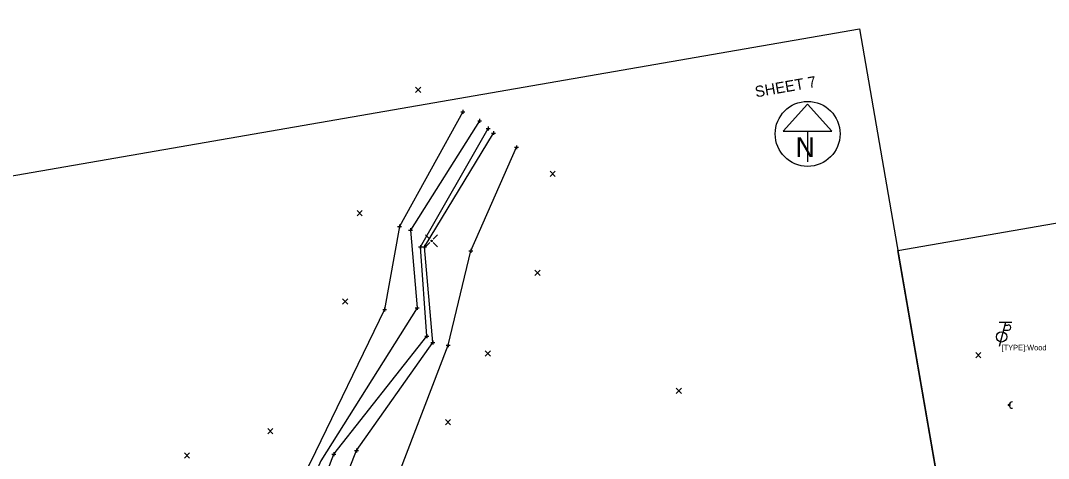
# Model space of a CAD drawing. Extents: x 1386013 to 1389776, y 604170 to 607009.
# Drawn here: x 1388473.5 to 1388733.1, y 605068.3 to 605178.8 of the extents above; entities that cross this region are included whole.
import ezdxf

# ---------------------------------------------------------------- set-up
doc = ezdxf.new("R2010")
doc.units = 0
for name, color, linetype in [('DR_X_Ditch', 7, 'Continuous'), ('DV_X_Text', 7, 'Continuous'), ('RW_P_Esmt_SH', 7, 'Continuous'), ('SH_Cut_Line', 7, 'Continuous'), ('SH_Masking', 7, 'Continuous'), ('SH_Text', 7, 'Continuous'), ('SV_P_Mon_Cells_Set', 7, 'Continuous'), ('SV_X_Random_Point', 7, 'Continuous'), ('SV_X_Text', 7, 'Continuous'), ('SV_X_Toe_of_Slope', 7, 'Continuous'), ('SV_X_Top_of_Bank', 7, 'Continuous')]:
    doc.layers.add(name, color=color, linetype=linetype)

msp = doc.modelspace()

# ---------------------------------------------------------------- linework, layer by layer
at = {"layer": 'DR_X_Ditch'}
msp.add_lwpolyline([(1388537.98, 605027.37), (1388541.71, 605041.08), (1388552.63, 605069.45), (1388576.08, 605099.21), (1388574.46, 605121.7), (1388591.59, 605151.63)], dxfattribs=at)
at = {"layer": 'DV_X_Text'}
for p, q in [((1388584.72, 605155.83), (1388585.72, 605155.83)), ((1388585.22, 605156.33), (1388585.22, 605155.33)), ((1388585.22, 605155.83), (1388585.22, 605155.83)), ((1388588.94, 605153.52), (1388589.94, 605153.52)), ((1388589.44, 605154.02), (1388589.44, 605153.02)), ((1388589.44, 605153.52), (1388589.44, 605153.52)), ((1388591.09, 605151.63), (1388592.09, 605151.63)), ((1388591.59, 605152.13), (1388591.59, 605151.13)), ((1388591.59, 605151.63), (1388591.59, 605151.63)), ((1388592.43, 605150.46), (1388593.43, 605150.46)), ((1388592.93, 605150.96), (1388592.93, 605149.96)), ((1388592.93, 605150.46), (1388592.93, 605150.46)), ((1388598.78, 605147.35), (1388598.78, 605146.35)), ((1388598.28, 605146.85), (1388599.28, 605146.85)), ((1388598.78, 605146.85), (1388598.78, 605146.85)), ((1388568.7, 605126.91), (1388569.7, 605126.91)), ((1388569.2, 605127.41), (1388569.2, 605126.41)), ((1388569.2, 605126.91), (1388569.2, 605126.91)), ((1388571.45, 605125.96), (1388572.45, 605125.96)), ((1388571.95, 605126.46), (1388571.95, 605125.46)), ((1388571.95, 605125.96), (1388571.95, 605125.96)), ((1388573.96, 605121.7), (1388574.96, 605121.7)), ((1388574.46, 605122.2), (1388574.46, 605121.2)), ((1388574.46, 605121.7), (1388574.46, 605121.7)), ((1388574.99, 605121.74), (1388575.99, 605121.74)), ((1388575.49, 605122.24), (1388575.49, 605121.24)), ((1388575.49, 605121.74), (1388575.49, 605121.74)), ((1388586.73, 605120.73), (1388587.73, 605120.73)), ((1388587.23, 605121.23), (1388587.23, 605120.23)), ((1388587.23, 605120.73), (1388587.23, 605120.73)), ((1388564.94, 605105.9), (1388565.94, 605105.9)), ((1388565.44, 605106.4), (1388565.44, 605105.4)), ((1388565.44, 605105.9), (1388565.44, 605105.9)), ((1388573.18, 605106.31), (1388574.18, 605106.31)), ((1388573.68, 605106.81), (1388573.68, 605105.81)), ((1388573.68, 605106.31), (1388573.68, 605106.31)), ((1388575.58, 605099.21), (1388576.58, 605099.21)), ((1388576.08, 605099.71), (1388576.08, 605098.71)), ((1388576.08, 605099.21), (1388576.08, 605099.21)), ((1388577.59, 605098.1), (1388577.59, 605097.1)), ((1388577.09, 605097.6), (1388578.09, 605097.6)), ((1388577.59, 605097.6), (1388577.59, 605097.6)), ((1388581, 605096.94), (1388582, 605096.94)), ((1388581.5, 605097.44), (1388581.5, 605096.44)), ((1388581.5, 605096.94), (1388581.5, 605096.94)), ((1388552.63, 605069.95), (1388552.63, 605068.95)), ((1388557.84, 605070.32), (1388558.84, 605070.32)), ((1388558.34, 605070.82), (1388558.34, 605069.82)), ((1388558.34, 605070.32), (1388558.34, 605070.32)), ((1388552.13, 605069.45), (1388553.13, 605069.45)), ((1388552.63, 605069.45), (1388552.63, 605069.45))]:
    msp.add_line(p, q, dxfattribs=at)
at = {"layer": 'RW_P_Esmt_SH'}
for p, q in [((1388575.79, 605124.73), (1388576.88, 605123.64)), ((1388577.71, 605123.64), (1388578.8, 605124.73)), ((1388575.79, 605121.71), (1388576.88, 605122.81)), ((1388577.71, 605122.81), (1388578.8, 605121.71))]:
    msp.add_line(p, q, dxfattribs=at)
msp.add_circle((1388577.3, 605123.23), 0.17, dxfattribs=at)
at = {"layer": 'SH_Cut_Line'}
for points in [[(1388732.63, 604904.03), (1388695.08, 605120.8), (1389030.09, 605178.83), (1389067.64, 604962.06)], [(1388387.93, 604901.94), (1388350.38, 605118.71), (1388685.39, 605176.74), (1388722.94, 604959.97)]]:
    msp.add_lwpolyline(points, close=True, dxfattribs=at)
at = {"layer": 'SH_Masking'}
msp.add_circle((1388672.29, 605150.24), 8.2, dxfattribs=at)
at = {"layer": 'SH_Text'}
for p, q in [((1388672.29, 605157.71), (1388666.14, 605150.89)), ((1388678.44, 605150.89), (1388672.29, 605157.71)), ((1388666.14, 605150.89), (1388678.44, 605150.89)), ((1388672.29, 605150.89), (1388672.29, 605143.15))]:
    msp.add_line(p, q, dxfattribs=at)
msp.add_circle((1388672.29, 605150.24), 8.2, dxfattribs=at)
at = {"layer": 'SV_P_Mon_Cells_Set'}
for p, q in [((1388722.26, 605102.61), (1388720.65, 605096.61)), ((1388723.86, 605102.61), (1388720.66, 605102.61)), ((1388721.76, 605100.74), (1388722.95, 605100.74)), ((1388722.1, 605102.01), (1388722.95, 605102.01))]:
    msp.add_line(p, q, dxfattribs=at)
for centre, radius in [((1388721.29, 605099.01), 1.3), ((1388723.21, 605081.8), 0.2)]:
    msp.add_circle(centre, radius, dxfattribs=at)
for centre, radius, start, end in [((1388722.96, 605101.38), 0.638, 268.8767, 91.1233), ((1388724.01, 605081.8), 0.8, 90, 270)]:
    msp.add_arc(centre, radius, start, end, dxfattribs=at)
at = {"layer": 'SV_X_Random_Point'}
for p, q in [((1388573.24, 605160.7), (1388574.57, 605162.03)), ((1388573.24, 605162.03), (1388574.57, 605160.7)), ((1388607.21, 605139.51), (1388608.54, 605140.85)), ((1388607.21, 605140.85), (1388608.54, 605139.51)), ((1388558.47, 605129.56), (1388559.8, 605130.89)), ((1388558.47, 605130.89), (1388559.8, 605129.56)), ((1388603.35, 605114.49), (1388604.69, 605115.83)), ((1388603.35, 605115.83), (1388604.69, 605114.49)), ((1388554.79, 605107.29), (1388556.12, 605108.63)), ((1388554.79, 605108.63), (1388556.12, 605107.29)), ((1388590.81, 605094.14), (1388592.15, 605095.48)), ((1388590.81, 605095.48), (1388592.15, 605094.14)), ((1388714.74, 605093.74), (1388716.07, 605095.08)), ((1388714.74, 605095.08), (1388716.07, 605093.74)), ((1388639.09, 605084.73), (1388640.43, 605086.07)), ((1388639.09, 605086.07), (1388640.43, 605084.73)), ((1388580.77, 605076.86), (1388582.1, 605078.19)), ((1388580.77, 605078.19), (1388582.1, 605076.86)), ((1388535.9, 605074.58), (1388537.23, 605075.92)), ((1388535.9, 605075.92), (1388537.23, 605074.58)), ((1388514.85, 605068.43), (1388516.18, 605069.76)), ((1388514.85, 605069.76), (1388516.18, 605068.43))]:
    msp.add_line(p, q, dxfattribs=at)
at = {"layer": 'SV_X_Toe_of_Slope'}
for points in [[(1388589.44, 605153.52), (1388571.95, 605125.96), (1388573.68, 605106.31), (1388549.32, 605067.76), (1388539.47, 605045.01), (1388530.96, 605025.88)], [(1388545.71, 605028.3), (1388546.09, 605039.56), (1388558.34, 605070.32), (1388577.59, 605097.6), (1388575.49, 605121.74), (1388592.93, 605150.46)]]:
    msp.add_lwpolyline(points, dxfattribs=at)
at = {"layer": 'SV_X_Top_of_Bank'}
for points in [[(1388585.22, 605155.83), (1388569.2, 605126.91), (1388565.44, 605105.9), (1388546.66, 605067.19), (1388536.36, 605047.18), (1388527.54, 605025.43)], [(1388557.64, 605034.68), (1388569.01, 605064.45), (1388581.5, 605096.94), (1388587.23, 605120.73), (1388598.78, 605146.85)]]:
    msp.add_lwpolyline(points, dxfattribs=at)

# ---------------------------------------------------------------- texts
at = {"layer": 'SH_Text'}
msp.add_text('SHEET 7', height=2.8, rotation=9.8279, dxfattribs=at).set_placement((1388659.24, 605159.44))
msp.add_text('N', height=5, dxfattribs=at).set_placement((1388669.26, 605144.41))
at = {"layer": 'SV_X_Text'}
msp.add_text('[TYPE]:Wood', height=1.4, dxfattribs=at).set_placement((1388721.29, 605095.61))

doc.saveas('drawing.dxf')
